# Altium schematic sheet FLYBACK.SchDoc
size A3
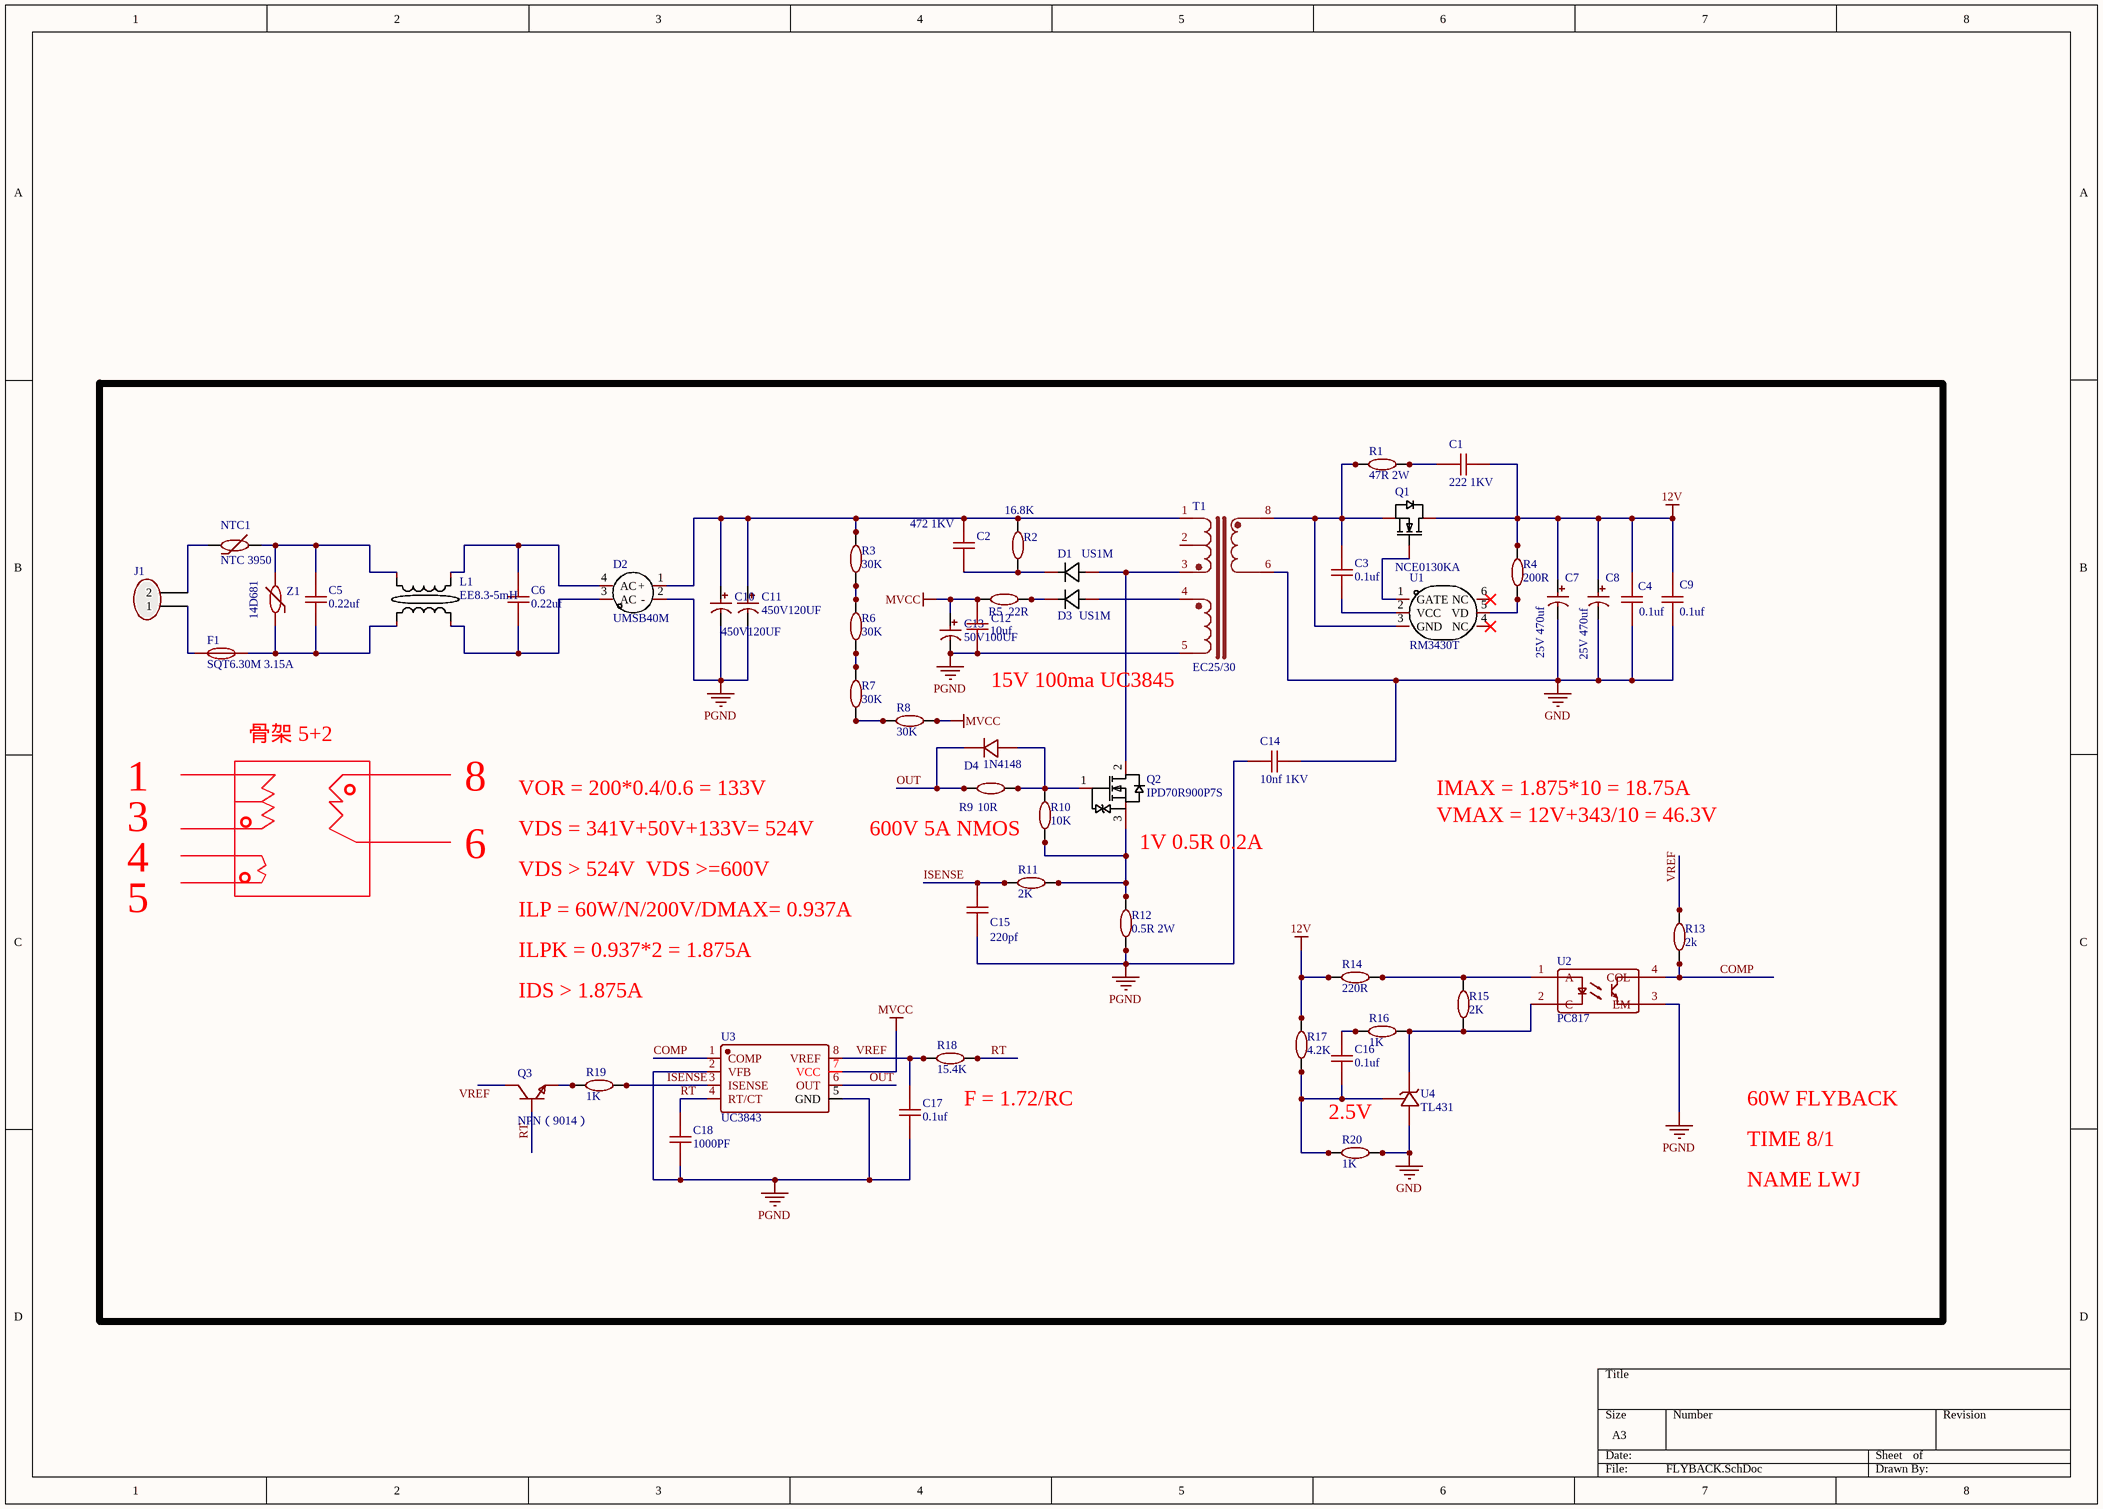
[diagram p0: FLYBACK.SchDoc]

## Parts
C1  222 1KV  [CBB-5.0]
C2  472 1KV  [C1206]
C3  0.1uf  [C0603]
C4  0.1uf  [C0603]
C5  0.22uf  [P10MM]
C6  0.22uf  [P10MM]
C7  25V 470uf  [8*12mm]
C8  25V 470uf  [8*12mm]
C9  0.1uf  [C0603]
C10  450V120UF  [400V 22UF 10*14]
C11  450V120UF  [16*20]
C12  10uf  [C0603]
C13  50V100UF  [8*12mm]
C14  10nf 1KV  [CBB-5.0]
C15  220pf  [C0603]
C16  0.1uf  [C0603]
C17  0.1uf  [C0603]
C18  1000PF  [C0603]
D1  US1M  [US1M]
D2  UMSB40M  [UMSB40M]
D3  US1M  [US1M]
D4  1N4148  [1N4148]
F1  SQT6.30M 3.15A  [SQT6.30M]
J1  (no value)  [AC- RT-C08-F2-WH]
L1  EE8.3-5mH  [EE8.3-5mH]
NTC1  NTC 3950  [NTC-5.0]
Q1  NCE0130KA  [NCE0130KA]
Q2  IPD70R900P7S  [IPD70R900P7S]
Q3  NPN（9014）  [SOT-23]
R1  47R 2W  [2512]
R2  16.8K  [R1W]
R3  30K  [R0805]
R4  200R  [R0603]
R5  22R  [R0603]
R6  30K  [R0805]
R7  30K  [R0805]
R8  30K  [R0805]
R9  10R  [R0603]
R10  10K  [R0603]
R11  2K  [R0603]
R12  0.5R 2W  [2512]
R13  2k  [R0603]
R14  220R  [R0603]
R15  2K  [R0603]
R16  1K  [R0603]
R17  4.2K  [R0603]
R18  15.4K  [R0603]
R19  1K  [R0603]
R20  1K  [R0603]
T1  EC25/30  [EE28]
U1  RM3430T  [RM3430T]
U2  PC817  [PC817SMD]
U3  UC3843  [UC3845]
U4  TL431  [tl431]
Z1  14D681  [CNR-10D561KBTSA]

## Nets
12V: C1.1 C4.1 C7.1 C8.1 C9.1 Q1.2(D) R4.1 R14.1 R17.1
GND: C4.2 C7.2 C8.2 C9.2 C14.1 R20.1 T1.6 U4.3(A)
MVCC: C12.1 C13.1 R5.2 R8.1 U3.7(VCC)
PGND: C10.2 C11.2 C12.2 C13.2 C14.2 C15.1 C17.1 C18.1 D2.2(-) R12.1 T1.5 U2.3(EM) U3.2(VFB) U3.5(GND)
COMP: R13.1 U2.4(COL) U3.1(COMP)
ISENSE: C15.2 R11.2 R19.2 U3.3(ISENSE)
OUT: D4.1(C) R9.2 U3.6(OUT)
RT: C18.2 Q3.1(B) R18.1 U3.4(RT/CT)
VREF: C17.2 Q3.3(C) R13.2 R18.2 U3.8(VREF)
NetC1_2: C1.2 R1.1
NetC2_1: C2.1 D1.2(K) R2.1
NetC2_2: C2.2 C10.1 C11.1 D2.1(+) R2.2 R3.2 T1.1
NetC3_1: C3.1 Q1.3(S) R1.2 T1.8 U1.3(GND)
NetC3_2: C3.2 U1.2(VCC)
NetC5_1: C5.1 L1.2 NTC1.2 Z1.2
NetC5_2: C5.2 F1.1 L1.3 Z1.1
NetC6_1: C6.1 D2.3(AC) L1.4
NetC6_2: C6.2 D2.4(AC) L1.1
NetC16_1: C16.1 R17.2 R20.2 U4.1(R)
NetC16_2: C16.2 R16.1
NetD1_1: D1.1(A) Q2.2(D) T1.3
NetD3_1: D3.1(A) T1.4
NetD3_2: D3.2(K) R5.1
NetD4_2: D4.2(A) Q2.1(G) R9.1 R10.1
NetF1_2: F1.2 J1.1
NetJ1_2: J1.2 NTC1.1
NetQ1_1: Q1.1(G) U1.1(GATE)
NetQ2_3: Q2.3(S) R10.2 R11.1 R12.2
NetQ3_2: Q3.2(E) R19.1
NetR3_1: R3.1 R6.2
NetR4_2: R4.2 U1.5(VD)
NetR6_1: R6.1 R7.2
NetR7_1: R7.1 R8.2
NetR14_2: R14.2 R15.2 U2.1(A)
NetR15_1: R15.1 R16.2 U2.2(C) U4.2(K)

Not connected (* = marked no-connect by the designer): T1 2; U1 4(NC)* 6(NC)*

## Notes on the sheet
- 15V 100ma UC3845
- 骨架 5+2
- 1
- 3
- 。
- 8
- VDS = 341V+50V+133V= 524V
- VOR = 200*0.4/0.6 = 133V
- 600V 5A NMOS
- (near Q2) 1V 0.5R 0.2A
- IMAX = 1.875*10 = 18.75A
- VMAX = 12V+343/10 = 46.3V
- 4
- 5
- 6
- VDS > 524V  VDS >=600V
- ILP = 60W/N/200V/DMAX= 0.937A
- ILPK = 0.937*2 = 1.875A
- IDS > 1.875A
- (near R18) F = 1.72/RC
- 2.5V
- 60W FLYBACK
- TIME 8/1
- NAME LWJ

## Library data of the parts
C1-C6 C9 C12 C14-C18 = 贴片电容
C7 C8 C10 C11 C13 = 贴片电解电容
D4 = 1N4007
F1 = SQT6.30M
J1 = 2P插针
R1-R20 = 贴片电阻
